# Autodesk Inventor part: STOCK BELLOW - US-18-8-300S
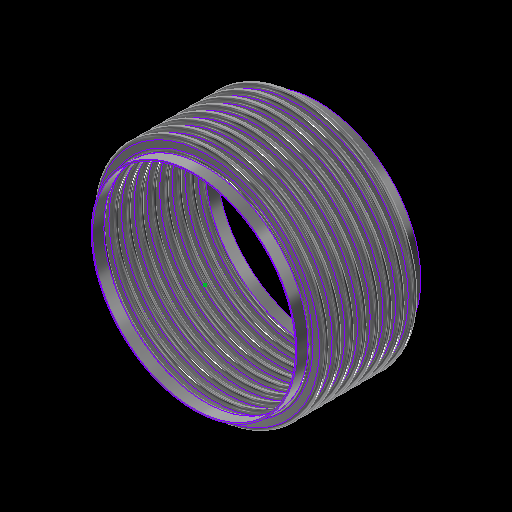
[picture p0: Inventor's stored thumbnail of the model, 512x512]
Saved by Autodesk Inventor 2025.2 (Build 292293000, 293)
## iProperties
Category: 16 GA (0.060 THICK)
RuleStatus: InUse
Created: 2024-01
Part Number: STOCK BELLOW - US-18-8-300S
Project: =STOCK BELLOWS: <Stock Number><SFILL>
Material: ASTM A240-304
Description: =STOCK BELLOWS: <Stock Number>, <SID_> I.D., <SOD_> O.D., <SPLY_> PLY, <Category>, <SNET_CONS> CONS.<PITCH_><STANGENT_> TANGENT<SFILL>
Document SubType Name: Sheet Metal
Designer: GS
Stock Number: U.S-18-8-300S
Surface Area: 19850.5 cm^2
Volume: 2984.92 cm^3
Sheet Metal Rule: Default
Appearance: STAINLESS STEEL
Mass: 24050.4 g
Density: 8.05729 g/cm^3
THK: 0.036
ID: 3.500
OD: 4.250
CONS_: 2
PITCH: 0.500
TANGENT: 0.500
BELLOWS_UPSET: 0.000
d79: 1.000
d82: 1.000
d83: 26.000
d84: 24.000
d174: 8
d214: 8
STHK_: 0.060
SID_: 18.000
SOD_: 20.500
SPITCH_: 1.125
STANGENT__: 1.000
SBELLOWS_UPSET_: 0.000
SDIFF_TAN: 1.000
d252: 2
d275: 2
d287: 0.050
d289: 0.500
d290: 0.000
SOD_NECK: 18 1/4
PLY: 1
PSET: 4.178
PBAR: 1.035
COUNTER: 1.500
NET_TUBE: 3.071
CONS: 2
S_CONS: 0
NET_CONS: 2
ID_M: 88.90 mm
OD_M: 107.95 mm
THK_M: 0.91 mm
ID_U: 3.500 in
OD_U: 4.250 in
THK_U: 0.036 in
TANGENT2: 0.500
TAN_TO_TAN: 1.000 in
d80: 2.571
d81: 10
SID: 2.375
SCONS_: 8
SPITCH: 0.250
STANGENT_: 1.000
SBELLOWS_UPSET: 0.000
SNET_CONS: 8
SS_CONS: 0
SCONS: 8
d190: 8
d191: 1
d192: 1
d193: 8
d194: 0
SIZE: 18.00
PRESSURE: 300
d230: 8
STANGENT: 4.000
SPLY_: 2
d233: 8
d234: 0
d263: 2
d265: 1
d268: 2
d269: 0
d286: 2
d288: 1
d291: 2
d292: 0
SREROLL: 0.750
BLETP: 0.000 ul
PRES_Copy: 85
MATTABLE: 20 GA (0.036 THICK)
PART_NUMBER: U.S-18-8-300S
PITCH_: =, <SPITCH_> PITCH,
CFILL: .
SFILL: .
MESH: ,
COMP: 1.53
EXT: 0.77
LAT: 0.23
ANG: 516
ASR: 10621
LSR: 72883
ANSR: 8586
PRES: 300
COMPM: 15.3
EXTM: 7.65
LATM: 2.30
ASRM: 1860.056
PRESM: 20.684
LSRM: 12764.000
ANSRM: 1503.666
TEMPMIN: 20
TEMPMAX: 800
TEMPMINM: -7
TEMPMAXM: 427
WEIGHTM: 24.050
WEIGHT: 53.022
Author: GS
Keywords: 20 GA (0.036 THICK)
Comments: =STOCK BELLOW - <STOCK NUMBER>
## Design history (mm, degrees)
sketch "Sketch2"
  geometry: L1 (0, -177.245)-(0, 562.856) reference; L2 (45.364, 0)-(44.45, 0); L3 (48.082, -2.718)-(50.343, -2.718); L4 (48.082, -3.632)-(50.343, -3.632); L5 (50.343, -9.982)-(48.082, -9.982); L6 (50.343, -9.068)-(48.082, -9.068); L7 (45.364, -12.7)-(44.45, -12.7); L8 (48.082, 0)-(48.082, -12.7); L9 (50.343, -6.35)-(53.975, -6.35); L10 (44.45, 0)-(44.45, -12.7); L11 (20.376, 102.841)-(20.376, 101.926); L12 (58.262, 457.127)-(58.262, 349.177); L13 (58.262, 444.427)-(58.262, 336.477); L14 (93.133, -58.817)-(93.133, -71.517); L15 (118.746, -66.401)-(118.746, -66.401); L16 (50.343, -9.068)-(50.343, -9.982); L17 (48.082, -9.068)-(48.082, -9.982); L18 (48.082, -9.525)-(50.343, -9.525); L19 (53.975, 0)-(53.975, -12.7); L20 (-50.343, -9.068)-(-50.343, -9.982); L21 (-50.343, -2.718)-(-48.082, -2.718); L22 (-50.343, -3.632)-(-48.082, -3.632); L23 (-48.082, -9.068)-(-50.343, -9.068); L24 (-50.343, -9.525)-(-48.082, -9.525); L25 (-48.082, -9.982)-(-50.343, -9.982); L26 (-48.082, -9.068)-(-48.082, -9.982); L27 (-44.45, 0.653)-(-44.45, -12.047); L28 (-48.082, -6.35)-(-44.45, -6.35); L29 (-50.343, 0.653)-(-50.343, -12.7); L30 (-53.061, 0)-(-53.975, 0); L31 (-53.975, 0)-(-53.975, -12.7); L32 (-53.061, -12.7)-(-53.975, -12.7); A1 r 2.718 centre (48.082, 0) between (45.364, 0) and (48.082, -2.718); A2 r 3.632 centre (48.082, 0) between (44.45, 0) and (48.082, -3.632); A3 r 3.632 centre (50.343, -6.35) between (50.343, -9.982) and (50.343, -2.718); A4 r 2.718 centre (50.343, -6.35) between (50.343, -9.068) and (50.343, -3.632); A5 r 2.718 centre (48.082, -12.7) between (48.082, -9.982) and (45.364, -12.7); A6 r 3.632 centre (48.082, -12.7) between (48.082, -9.068) and (44.45, -12.7); A7 r 3.175 centre (50.343, -6.35) between (50.343, -9.525) and (53.518, -6.35); A8 r 3.175 centre (48.082, -12.7) between (48.082, -9.525) and (44.907, -12.7); A9 r 2.718 centre (-50.343, -12.7) between (-50.343, -9.982) and (-53.061, -12.7); A10 r 2.718 centre (-48.082, -6.35) between (-48.082, -9.068) and (-48.082, -3.632); A11 r 3.175 centre (-48.082, -6.35) between (-48.082, -9.525) and (-44.907, -6.35); A12 r 3.632 centre (-48.082, -6.35) between (-48.082, -9.982) and (-48.082, -2.718); A13 r 3.175 centre (-50.343, -12.7) between (-50.343, -9.525) and (-53.518, -12.7); A14 r 3.632 centre (-50.343, -12.7) between (-50.343, -9.068) and (-53.975, -12.7); A15 r 2.718 centre (-50.343, 0) between (-53.061, 0) and (-50.343, -2.718); A16 r 3.632 centre (-50.343, 0) between (-53.975, 0) and (-50.343, -3.632); 10 further points
  constraints: 62 end point, 38 point on circle, 20 tangent, 16 centre point, 12 parallel, 9 midpoint, 7 vertical, 6 coincident, 6 concentric, 6 point on line, 4 equal radius, 4 perpendicular, 3 horizontal, 1 collinear, 1 horizontal alignment, 10 other
  dimensions: "THK" = 0.9144 distance of L11.start L11.end; "ID" = 88.9 distance of L11.end point (20.376, 13.026); "OD" = 107.95 distance of L12.start L12.end; "PITCH" = 12.7 distance of L12.start L13.start; "TANGENT" = 12.7 distance of L14.start L14.end; "BELLOWS_UPSET" = 0 distance of L15.start L15.end; "d43" = 88.9 diameter of L10 L1 (= ID); "d44" = 107.95 diameter of L9.end L1 (= OD); "d45" = 0.9144 distance between parallel lines of L5 L6 (computed from THK, PLY); "d46" = 3.6322 radius of A3 (computed from PITCH, THK, PLY); "UPSET_PITCH" = 12.7 distance of L2.end L7.end (derived); "SIDEWALL_ANGLE" = 360 deg dimension on L3 L9 (derived); "CON_GAP" = 5.4356 distance of point (48.082, -9.068) point (48.082, -3.632) (derived); "TAN1" = 4.98728 dimension on A8 (derived); "TAN2" = 4.98728 dimension on A7 (derived); "LEG1" = 2.2606 distance of L18.start L18.end (derived); "d278" = 0.9144 distance between parallel lines of L25 L23 (derived); "d279" = 3.6322 radius of A12 (derived); "d280" = 12.7 distance of L30.end L31.end (derived); "d281" = 360 deg dimension on L21 L28 (derived); "d282" = 5.4356 distance of point (-50.343, -9.068) point (-50.343, -3.632) (derived); "d283" = 4.98728 dimension on A13 (derived); "d284" = 4.98728 dimension on A11 (derived); "d285" = 2.2606 distance of L24.start L24.end (derived); "d293" = 88.9 diameter of L27 L1 (derived); "d294" = 107.95 diameter of L31 L1 (derived)
  node "Sketch Rectangular Pattern1" dims "d31" = 25.4, "ID" = 88.9
  node "Sketch Rectangular Pattern2" dims "d39" = 25.4, "PITCH" = 12.7
revolve "CONS" stored, may be unused: angle "d48" = 90 deg
node "BELLOW MIDPLANE"
pattern_linear "Rectangular Pattern2" dims "d52" = 12.7 (= UPSET_PITCH)
sketch "Sketch5"
  geometry: C1 r 45.364 at (0, 0) reference; C2 r 44.45 at (0, 0) reference
extrude "TANGENT" new body sketch "Sketch5" distance "d53" = 12.7 (= TANGENT); taper "d54" = 0 deg
revolve "SAMETAN" stored, may be unused: angle "d65" = 90 deg
revolve "DIFFTAN" stored, may be unused: angle "d70" = 90 deg
sketch "Sketch9"
  geometry: L1 (53.319, 0)-(-53.319, 0) reference; L2 (0, -17.78)-(0, 17.78) reference; L3 (38.085, 0)-(-38.085, 0); L4 (38.085, -11.906)-(38.085, 11.906); L5 (25.385, -11.906)-(25.385, 11.906); L6 (13.15, 11.906)-(13.15, -11.906); L7 (-25.385, -11.906)-(-25.385, 11.906); L8 (-38.085, -11.906)-(-38.085, 11.906); L9 (37.291, -11.906)-(37.291, 11.906); L10 (38.085, -11.906)-(37.291, -11.906); L11 (38.085, 11.906)-(37.291, 11.906); L12 (13.546, 11.906)-(12.753, 11.906); L13 (12.753, 11.906)-(12.753, -11.906); L14 (12.753, -11.906)-(13.546, -11.906); L15 (13.546, -11.906)-(13.546, 11.906); L16 (-13.546, 11.906)-(-13.546, -11.906); L17 (-13.15, 11.906)-(-13.15, -11.906); L18 (-13.546, -11.906)-(-12.753, -11.906); L19 (-12.753, -11.906)-(-12.753, 11.906); L20 (-12.753, 11.906)-(-13.546, 11.906); L21 (-38.085, -11.906)-(-37.291, -11.906); L22 (-37.291, -11.906)-(-37.291, 11.906); L23 (-37.291, 11.906)-(-38.085, 11.906); L24 (-38.085, 11.906)-(-38.085, -11.906); L25 (38.085, -0.397)-(-38.085, -0.397); L26 (-38.085, -0.397)-(-38.085, 0.397); L27 (-38.085, 0.397)-(38.085, 0.397); L28 (38.085, 0.397)-(38.085, -0.397); L29 (-38.085, 11.906)-(38.085, 11.906); L30 (38.085, 11.906)-(38.085, 12.7); L31 (38.085, 12.7)-(-38.085, 12.7); L32 (-38.085, 12.7)-(-38.085, 11.906); L33 (38.085, -11.906)-(-38.085, -11.906); L34 (-38.085, -11.906)-(-38.085, -12.7); L35 (-38.085, -12.7)-(38.085, -12.7); L36 (38.085, -12.7)-(38.085, -11.906); 30 further points
  constraints: 68 end point, 13 midpoint, 13 parallel, 8 horizontal, 7 perpendicular, 6 equal length, 3 point on line, 2 vertical, 14 other
  dimensions: "d115" = 23.8125 distance of L4.start L4.end (derived); "d116" = 12.7 distance between parallel lines of L4 L5 (derived); "d117" = 12.23516 distance between parallel lines of L5 L6 (derived); "d125" = 38.53427 distance between parallel lines of L7 L6 (derived); "d127" = 12.7 distance between parallel lines of L8 L7 (derived); "d128" = 24.93516 distance between parallel lines of L6 L4 (derived); "d130" = 76.16943 distance between parallel lines of L8 L4 (derived); "RULER_THK" = 0.79375 distance between parallel lines of L4 L9; "d135" = 0.79375 distance of L13.end L14.end (derived); "d138" = 26.29911 distance of L13.end L16.end (derived); "d143" = 0.79375 distance of L22.end L8.end (derived); "d144" = 0.79375 distance between parallel lines of L27 L25 (derived)
extrude "RULER" join sketch "Sketch9" distance "d149" = 0.79375 (derived); taper "d150" = 0 deg
extrude "BARS" join sketch "Sketch9" distance "d151" = 0.79375 (derived); taper "d152" = 0 deg
pattern_linear "Rectangular Pattern4" dims "d155" = 26.29911 (derived)
sketch "Sketch13"
  geometry: L1 (93.149, -52.467)-(93.149, -77.867); L2 (231.648, 0)-(228.6, 0); L3 (231.648, -28.575)-(228.6, -28.575); L4 (251.682, -22.955)-(237.268, -22.955); L5 (251.682, -19.907)-(237.268, -19.907); L6 (251.682, -14.287)-(260.35, -14.287); L7 (237.268, -5.62)-(251.682, -5.62); L8 (237.268, 0)-(237.268, -28.575); L9 (228.6, 0)-(228.6, -28.575); L10 (58.254, 24.269)-(58.254, -496.431); L11 (58.254, -4.306)-(58.254, -525.006); L12 (58.254, -61.456)-(58.254, -582.156); L13 (58.254, -90.031)-(58.254, -610.731); L14 (58.254, -118.606)-(58.254, -639.306); L15 (58.254, -147.181)-(58.254, -667.881); L16 (58.254, -175.756)-(58.254, -696.456); L17 (58.254, -32.881)-(58.254, -553.581); L18 (20.376, 103.45)-(20.376, 101.926); L19 (237.268, -8.668)-(251.682, -8.668); L20 (0, -856.437)-(0, 263.431) reference; L21 (-52.07, 0)-(312.42, 0) reference; A1 r 5.62 centre (237.268, 0) between (231.648, 0) and (237.268, -5.62); A2 r 5.62 centre (237.268, -28.575) between (237.268, -22.955) and (231.648, -28.575); A3 r 8.668 centre (237.268, -28.575) between (237.268, -19.907) and (228.6, -28.575); A4 r 5.62 centre (251.682, -14.287) between (251.682, -19.907) and (251.682, -8.668); A5 r 8.668 centre (251.682, -14.287) between (251.682, -22.955) and (251.682, -5.62); A6 r 8.668 centre (237.268, 0) between (228.6, 0) and (237.268, -8.668); 6 further points; 1 other entity
  constraints: 38 end point, 15 point on circle, 9 tangent, 6 centre point, 6 parallel, 5 vertical alignment, 4 point on line, 4 vertical, 3 coincident, 3 concentric, 2 collinear, 2 equal radius, 1 horizontal, 1 perpendicular, 23 other
  dimensions: "SBELLOWS_UPSET_" = 0 distance of point (118.762, -66.401) point (118.762, -66.401); "STOTAL_THK_BELLOW__" = 3.048 distance between parallel lines of L4 L5 (derived); "d224" = 8.66775 radius of A5 (derived); "d225" = 28.575 distance of L2.end L3.end (derived); "SSIDEWALL_ANGLE_" = 360 deg dimension on L7 L6 (derived); "SSCON_GAP_" = 11.2395 distance of point (237.268, -19.907) point (237.268, -8.668) (derived); "d235" = 457.2 diameter of L9 L20 (derived); "d236" = 520.7 diameter of L6.end L20 (derived)
  node "Sketch Rectangular Pattern4" dims "d228" = 25.4
  node "Sketch Rectangular Pattern5" dims "d229" = 25.4
revolve "SBELLOW" stored, may be unused: angle "d197" = 90 deg
pattern_linear "Rectangular Pattern5" dims "d204" = 28.575 (derived)
revolve "STANGENT" stored, may be unused: angle "d240" = 90 deg
revolve "SSAMETAN" stored, may be unused: angle "d241" = 90 deg
revolve "SDIFFTAN" stored, may be unused: angle "d246" = 90 deg
revolve "INVCON" stored, may be unused: angle "d295" = 90 deg
pattern_linear "Rectangular Pattern6" dims "d298" = 12.7 (derived)
revolve "INVTANGENT" stored, may be unused: angle "d302" = 90 deg
revolve "INVSAMETAN" stored, may be unused: angle "d307" = 90 deg
revolve "INVDIFFTAN" stored, may be unused: angle "d312" = 90 deg
sketch "ID BELLOW MOUNT CALC"
  geometry: L1 (44.45, 0)-(38.1, 0); L2 (38.1, 0)-(38.1, 12.7); L3 (38.1, 12.7)-(44.45, 12.7); L4 (44.45, 12.7)-(44.45, 0); L5 (36.513, 12.7)-(35.598, 12.7); L6 (35.598, 12.7)-(35.598, 0); L7 (35.598, 0)-(36.513, 0); L8 (36.513, 0)-(36.513, 12.7); L9 (0, -2.54)-(0, 15.24) reference; L10 (-8.89, 0)-(53.34, 0) reference; 1 further point
  constraints: 16 end point, 5 parallel, 2 collinear, 2 horizontal, 2 perpendicular
  dimensions: "d314" = 12.7 distance of L5.end L6.end (derived); "d315" = 0.9144 distance of L5.start L5.end (derived); "IG" = 1.5875 distance between parallel lines of L2 L8; "PIPE_OD" = 88.9 diameter of L4 L9; "PIPE_WALL" = 6.35 distance of L2.end L3.end; "ID_MT_BELLOW" = 71.1962 diameter of L6 L9 (derived)
revolve "CFILL" stored, may be unused: angle "d320" = 90 deg
pattern_linear "Rectangular Pattern7" dims "d323" = 12.7 (derived)
revolve "SFILL" stored, may be unused: angle "d324" = 90 deg
pattern_linear "Rectangular Pattern8" dims "d327" = 28.575 (derived)
node "STOCK BELLOW MIDPLANE"
node "BELLOW"
sketch "Sketch6"
  geometry: L1 (-12.7, 45.364)-(0, 45.364); L2 (0, 45.364)-(0, 44.45); L3 (0, 44.45)-(-12.7, 44.45); L4 (-12.7, 44.45)-(-12.7, 45.364); L5 (10.16, 0)-(-60.96, 0) reference; L6 (-38.1, -89.422)-(-38.1, 153.44) reference; 1 further point
  constraints: 8 end point, 2 parallel, 1 horizontal, 1 perpendicular
  dimensions: "d61" = 12.7 distance of L2.end L3.end (derived); "d62" = 0.9144 distance of L1.end L2.end (derived); "d63" = 88.9 diameter of L3 L5 (derived); "d64" = 25.4 distance between parallel lines of L4 L6 (derived)
sketch "Sketch12"
  geometry: 1 further point
sketch "Sketch14"
  geometry: L1 (-25.4, 231.648)-(0, 231.648); L2 (0, 231.648)-(0, 228.6); L3 (0, 228.6)-(-25.4, 228.6); L4 (-25.4, 228.6)-(-25.4, 231.648); L5 (5.08, 0)-(-30.48, 0) reference; L6 (0, -46.33)-(0, 277.978) reference; 1 further point
  constraints: 8 end point, 2 parallel, 1 collinear, 1 horizontal, 1 perpendicular
  dimensions: "d237" = 3.048 distance of L3.end L1.start (derived); "d238" = 457.2 diameter of L3 L5 (derived); "d239" = 25.4 distance of L1.start L1.end (derived); "SOD_NECK" = 463.296 diameter of L1 L5 (derived)
sketch "Sketch15"
  geometry: L1 (-46.33, 0)-(277.978, 0) reference; L2 (228.6, -228.6)-(231.648, -228.6); L3 (231.648, -228.6)-(231.648, -254); L4 (231.648, -254)-(228.6, -254); L5 (228.6, -254)-(228.6, -228.6); L6 (0, -307.34)-(0, 66.04) reference; 1 further point
  constraints: 8 end point, 2 parallel, 1 horizontal, 1 perpendicular
  dimensions: "d205" = 25.4 distance of L4.end L2.start (derived); "d206" = 3.048 distance of L3.end L4.end (derived); "d207" = 457.2 diameter of L5 L6 (derived); "d208" = 228.6 distance between parallel lines of L1 L2 (derived)
node "TANGENT_"
node "SAME_TAN"
sketch "Sketch8"
  geometry: L1 (45.364, -25.4)-(44.45, -25.4); L2 (44.45, -25.4)-(44.45, -38.1); L3 (44.45, -38.1)-(45.364, -38.1); L4 (45.364, -38.1)-(45.364, -25.4); L5 (0, -48.26)-(0, 22.86) reference; L6 (-89.422, 0)-(153.44, 0) reference; 1 further point
  constraints: 8 end point, 2 parallel, 1 horizontal, 1 perpendicular
  dimensions: "d66" = 88.9 diameter of L2 L5 (derived); "TOTAL_THK_BELLOW" = 0.9144 distance of L2.end L3.end (derived); "d68" = 25.4 distance between parallel lines of L1 L6 (derived); "d69" = 12.7 distance of L1.end L2.end (derived)
node "DIFF_TAN"
node "Sketch Rectangular Pattern3" dims "d138" = 26.29911 (derived), "d141" = 25.4
node "SBELLOW_"
node "STANGENT_"
node "SSAME_TAN"
sketch "Sketch16"
  geometry: L1 (231.648, -228.6)-(228.6, -228.6); L2 (228.6, -228.6)-(228.6, -254); L3 (228.6, -254)-(231.648, -254); L4 (231.648, -254)-(231.648, -228.6); L5 (0, -307.34)-(0, 66.04) reference; L6 (-46.33, 0)-(277.978, 0) reference; 1 further point
  constraints: 8 end point, 2 parallel, 1 horizontal, 1 perpendicular
  dimensions: "SDIFF_TAN" = 25.4 distance of L3.end L1.start; "d243" = 3.048 distance of L2.end L3.end (derived); "d244" = 228.6 distance between parallel lines of L1 L6 (derived); "d245" = 457.2 diameter of L2 L5 (derived)
node "SDIFF_TAN"
body "Solid15"
sketch "Sketch17"
  geometry: L1 (53.975, 12.7)-(53.061, 12.7); L2 (53.061, 12.7)-(53.061, 0); L3 (53.061, 0)-(53.975, 0); L4 (53.975, 0)-(53.975, 12.7); L5 (0, -2.54)-(0, 15.24) reference; L6 (-10.795, 0)-(64.77, 0) reference; 2 further points
  constraints: 8 end point, 2 parallel, 1 horizontal, 1 midpoint, 1 perpendicular, 1 point on line
  dimensions: "INVTANGENT" = 12.7 distance of L3.end L1.start (derived); "d300" = 0.9144 distance of L1.start L1.end (derived); "d301" = 107.95 diameter of L4 L5 (derived)
body "Solid16"
sketch "Sketch18"
  geometry: L1 (53.975, -25.4)-(53.061, -25.4); L2 (53.061, -25.4)-(53.061, -38.1); L3 (53.061, -38.1)-(53.975, -38.1); L4 (53.975, -38.1)-(53.975, -25.4); L5 (-10.795, 0)-(64.77, 0) reference; L6 (0, -48.26)-(0, 22.86) reference; 1 further point
  constraints: 8 end point, 2 parallel, 1 horizontal, 1 perpendicular
  dimensions: "d303" = 25.4 distance between parallel lines of L1 L5 (derived); "d304" = 12.7 distance of L3.end L1.start (derived); "d305" = 0.9144 distance of L2.end L3.end (derived); "d306" = 107.95 diameter of L4 L6 (derived)
body "Solid17"
sketch "Sketch19"
  geometry: L1 (53.975, -25.4)-(53.061, -25.4); L2 (53.061, -25.4)-(53.061, -38.1); L3 (53.061, -38.1)-(53.975, -38.1); L4 (53.975, -38.1)-(53.975, -25.4); L5 (0, -48.26)-(0, 22.86) reference; L6 (-10.795, 0)-(64.77, 0) reference; 1 further point
  constraints: 8 end point, 2 parallel, 1 horizontal, 1 perpendicular
  dimensions: "d308" = 12.7 distance of L1.end L2.end (derived); "d309" = 107.95 diameter of L4 L5 (derived); "d310" = 0.9144 distance of L2.end L3.end (derived); "d311" = 25.4 distance between parallel lines of L1 L6 (derived)
body "Solid18"
body "Solid19"
body "Solid20"
other parameters: "BMPL" = -114.3, "PSET" = 106.1212 (computed from OD, THK, PLY) [user parameter], "PBAR" = 26.29911 (= 0.570796 x PITCH + OD - ID) [user parameter; used in 1 equation term], "COUNTER" = 15 [user parameter], "NET_TUBE" = 77.99823 (computed from CONS_, PBAR, TANGENT) [user parameter], "S_CONS" = 0 [user parameter; used in 1 equation term], "ID_M" = 88.9 (= ID) [user parameter], "OD_M" = 107.95 (= OD) [user parameter], "THK_M" = 0.9144 (= THK) [user parameter], "ID_U" = 88.9 (= ID) [user parameter], "OD_U" = 107.95 (= OD) [user parameter], "THK_U" = 0.9144 (= THK) [user parameter], "D_UNITS" = 0 [user parameter], "TANGENT2" = 12.7 [user parameter], "TAN_TO_TAN" = 25.4 [user parameter], "OD_NECK" = 90.7288 [user parameter], "d79" = 25.4, "d80" = 65.29823 [user parameter], "d82" = 25.4, "d83" = 660.4, "d84" = 609.6, "sa_0" = 4, "FRAME_THK" = 0.79375 [user parameter], "CON_FLAT" = 12.23516 [user parameter], "SID" = 60.325 [user parameter], "SPITCH" = 6.35 [user parameter], "STANGENT_" = 25.4 [user parameter], "SBELLOWS_UPSET" = 0 [user parameter], "SS_CONS" = 0 [user parameter], "STAN_TO_TAN_" = 228.6 [user parameter], "d100" = 3.048 [user parameter], "d191" = 25.4 [user parameter], "d194" = 0 [user parameter], "STANGENT" = 101.6 [user parameter], "d234" = 0 [user parameter], "SUPSET_PITCH_" = 28.575 [user parameter], "d269" = 0 [user parameter], "d287" = 1.27, "d289" = 12.7, "d290" = 0, "d292" = 0 [user parameter], "Thickness" = 3.048 (derived), "KFactor" = 4.4, "BendRadius" = 3.048 (derived), "BendReliefWidth" = 3.048 (derived), "BendReliefDepth" = 1.524 (derived), "CornerReliefSize" = 12.192 (derived), "SeamGap" = 0.00508, "MinimumRemnant" = 6.096 (derived), "TransitionRadius" = 3.048 (derived), "JacobiRadiusSize" = 3.048 (derived), "GapSize" = 3.048 (derived), "SREROLL" = 19.05 [user parameter], "CUR_STK_PITCH" = 28.575 [user parameter], "d328" = -114.3 (derived), "ASR" = 106210 [user parameter], "LSR" = 728830 [user parameter], "ANSR" = 85860 [user parameter], "BLETP" = 0 [user parameter], "ASRM" = 18600.5573 [user parameter], "PRESM" = 206.83949 [user parameter], "LSRM" = 127639.9979 [user parameter], "ANSRM" = 15036.6618 [user parameter], "TEMPMIN" = 2664.83333 [user parameter], "TEMPMAX" = 6998.16667 [user parameter], "TEMPMINM" = 2664.83333 [user parameter], "TEMPMAXM" = 6998.16667 [user parameter], "WEIGHT" = 240.50354 [user parameter], "WEIGHTM" = 0.2405 [user parameter]
